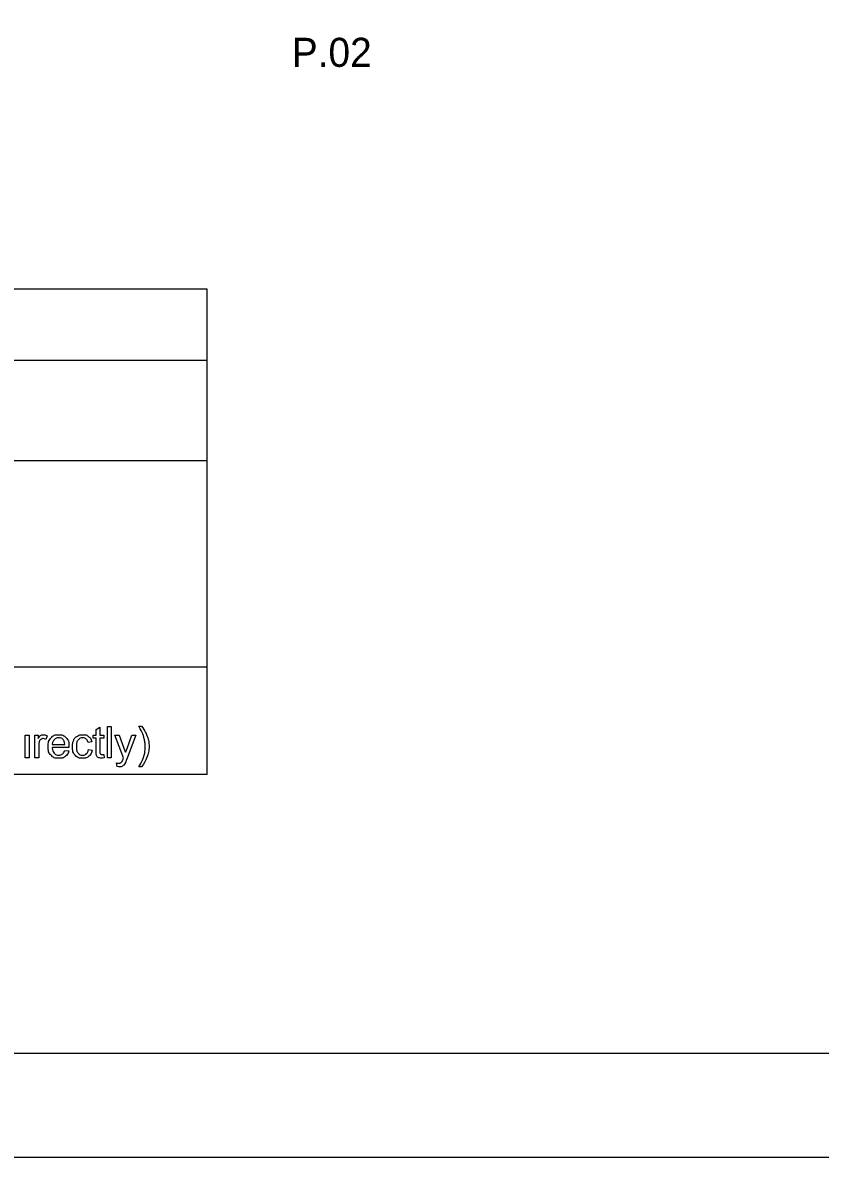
# Model space of a CAD drawing. Extents: x 0 to 34, y 0 to 22.
# Drawn here: x 5.74 to 9.58, y 0 to 5.46 of the extents above; entities that cross this region are included whole.
import ezdxf

# ---------------------------------------------------------------- set-up
doc = ezdxf.new("R2010")
doc.units = 0
for name, color, linetype in [('SH_Border', 7, 'Continuous'), ('SH_Cut_Line', 7, 'Continuous'), ('SH_Data', 7, 'Continuous'), ('SH_Text', 7, 'Continuous')]:
    doc.layers.add(name, color=color, linetype=linetype)

msp = doc.modelspace()

# ---------------------------------------------------------------- linework, layer by layer
at = {"layer": 'SH_Border'}
msp.add_lwpolyline([(1.5, 21.5), (33.5, 21.5), (33.5, 0.5), (1.5, 0.5)], close=True, dxfattribs=at)
at = {"layer": 'SH_Cut_Line'}
msp.add_lwpolyline([(0, 0), (34, 0), (34, 22), (0, 22)], close=True, dxfattribs=at)
at = {"layer": 'SH_Data'}
for p, q in [((6.6275, 4.1803), (2.3775, 4.1803)), ((6.6275, 1.8428), (6.6275, 4.1803)), ((2.3775, 3.8387), (6.6275, 3.8387)), ((2.3775, 3.3553), (6.6275, 3.3553)), ((6.6275, 2.3607), (2.3775, 2.3607)), ((6.6275, 1.8428), (2.3775, 1.8428))]:
    msp.add_line(p, q, dxfattribs=at)
at = {"layer": 'SH_Text'}
for points in [[(6.2974, 2.0766), (6.3105, 2.0766)], [(5.7509, 1.9239), (5.7509, 2.0328), (5.7693, 2.0328), (5.7693, 1.9239), (5.7509, 1.9239)], [(5.7971, 1.9239), (5.7971, 2.0328), (5.8137, 2.0328), (5.8137, 2.0163)], [(5.8562, 2.0293), (5.8497, 2.0122)], [(6.092, 1.9558), (6.092, 2.0185), (6.0784, 2.0185), (6.0784, 2.0328), (6.092, 2.0328), (6.092, 2.0597), (6.1105, 2.0708), (6.1105, 2.0328), (6.1289, 2.0328), (6.1289, 2.0185), (6.1105, 2.0185), (6.1105, 1.9547)], [(6.1465, 1.9239), (6.1465, 2.0741), (6.1649, 2.0741), (6.1649, 1.9239), (6.1465, 1.9239)], [(6.2243, 1.9238), (6.183, 2.0328), (6.2029, 2.0328), (6.2255, 1.9699)], [(6.241, 1.9693), (6.2643, 2.0328), (6.2827, 2.0328), (6.2414, 1.922)], [(5.8155, 1.9809), (5.8155, 1.9239), (5.7971, 1.9239)], [(5.9611, 1.9736), (5.88, 1.9736)], [(5.881, 1.9887), (5.9418, 1.9887)], [(6.0712, 2.0007), (6.0532, 1.998)], [(5.9416, 1.9591), (5.9606, 1.9567)], [(6.0548, 1.9638), (6.0729, 1.9613)], [(6.1289, 1.9404), (6.1315, 1.9241)], [(6.1928, 1.8821), (6.1907, 1.8995)], [(6.3105, 1.8798), (6.2974, 1.8798)]]:
    msp.add_lwpolyline(points, dxfattribs=at)
for points in [[(6.2974, 1.8798), (6.3279, 1.9289), (6.3279, 1.9782), (6.3279, 1.9974), (6.3235, 2.0164), (6.32, 2.0317), (6.3138, 2.0459), (6.3098, 2.0551), (6.2974, 2.0766)], [(6.3105, 2.0766), (6.3298, 2.0509), (6.339, 2.025), (6.3469, 2.0026), (6.3469, 1.9783), (6.3469, 1.9506), (6.3363, 1.9248), (6.3257, 1.899), (6.3105, 1.8798)], [(5.8137, 2.0163), (5.8201, 2.0278), (5.8254, 2.0315), (5.8308, 2.0352), (5.8372, 2.0352), (5.8466, 2.0352), (5.8562, 2.0293)], [(5.9606, 1.9567), (5.9561, 1.94), (5.9439, 1.9307), (5.9317, 1.9215), (5.9128, 1.9215), (5.8889, 1.9215), (5.875, 1.9362), (5.861, 1.9509), (5.861, 1.9774), (5.861, 2.0049), (5.8751, 2.02), (5.8892, 2.0352), (5.9118, 2.0352), (5.9336, 2.0352), (5.9474, 2.0203), (5.9612, 2.0055), (5.9612, 1.9785), (5.9612, 1.9769), (5.9611, 1.9736)], [(6.0729, 1.9613), (6.07, 1.9427), (6.0577, 1.9321), (6.0455, 1.9215), (6.0277, 1.9215), (6.0053, 1.9215), (5.9917, 1.9361), (5.9782, 1.9507), (5.9782, 1.9779), (5.9782, 1.9955), (5.984, 2.0088), (5.9899, 2.022), (6.0018, 2.0286), (6.0137, 2.0352), (6.0278, 2.0352), (6.0455, 2.0352), (6.0568, 2.0262), (6.068, 2.0172), (6.0712, 2.0007)], [(5.8497, 2.0122), (5.843, 2.0162), (5.8363, 2.0162), (5.8302, 2.0162), (5.8255, 2.0125), (5.8207, 2.0089), (5.8186, 2.0024), (5.8155, 1.9926), (5.8155, 1.9809)], [(5.88, 1.9736), (5.881, 1.9557), (5.8901, 1.9462), (5.8992, 1.9366), (5.9129, 1.9366), (5.923, 1.9366), (5.9302, 1.942), (5.9374, 1.9473), (5.9416, 1.9591)], [(5.9418, 1.9887), (5.9405, 2.0025), (5.9348, 2.0094), (5.926, 2.0201), (5.912, 2.0201), (5.8993, 2.0201), (5.8906, 2.0115), (5.8819, 2.003), (5.881, 1.9887)], [(6.0532, 1.998), (6.0507, 2.009), (6.0442, 2.0145), (6.0377, 2.0201), (6.0285, 2.0201), (6.0146, 2.0201), (6.0059, 2.0101), (5.9972, 2.0001), (5.9972, 1.9784), (5.9972, 1.9565), (6.0056, 1.9466), (6.014, 1.9366), (6.0275, 1.9366), (6.0384, 1.9366), (6.0456, 1.9433), (6.0529, 1.9499), (6.0548, 1.9638)], [(6.2255, 1.9699), (6.2299, 1.958), (6.2334, 1.9448), (6.2366, 1.9572), (6.241, 1.9693)], [(6.1315, 1.9241), (6.1238, 1.9224), (6.1176, 1.9224), (6.1076, 1.9224), (6.1021, 1.9256), (6.0965, 1.9288), (6.0943, 1.934), (6.092, 1.9392), (6.092, 1.9558)], [(6.1105, 1.9547), (6.1105, 1.9468), (6.1114, 1.9445), (6.1124, 1.9423), (6.1146, 1.9409), (6.1168, 1.9396), (6.1209, 1.9396), (6.1239, 1.9396), (6.1289, 1.9404)], [(6.1907, 1.8995), (6.1967, 1.8978), (6.2012, 1.8978), (6.2074, 1.8978), (6.211, 1.8999), (6.2147, 1.9019), (6.2171, 1.9056), (6.2188, 1.9084), (6.2227, 1.9193), (6.2232, 1.9209), (6.2243, 1.9238)], [(6.2414, 1.922), (6.2348, 1.9042), (6.2311, 1.8974), (6.2262, 1.8883), (6.2198, 1.8841), (6.2135, 1.8799), (6.2046, 1.8799), (6.1993, 1.8799), (6.1928, 1.8821)]]:
    msp.add_open_spline(points, degree=3, dxfattribs=at)

# ---------------------------------------------------------------- texts
msp.add_text('P.02', height=0.14, dxfattribs=at).set_placement((7.0344, 5.2511))

doc.saveas('drawing.dxf')
